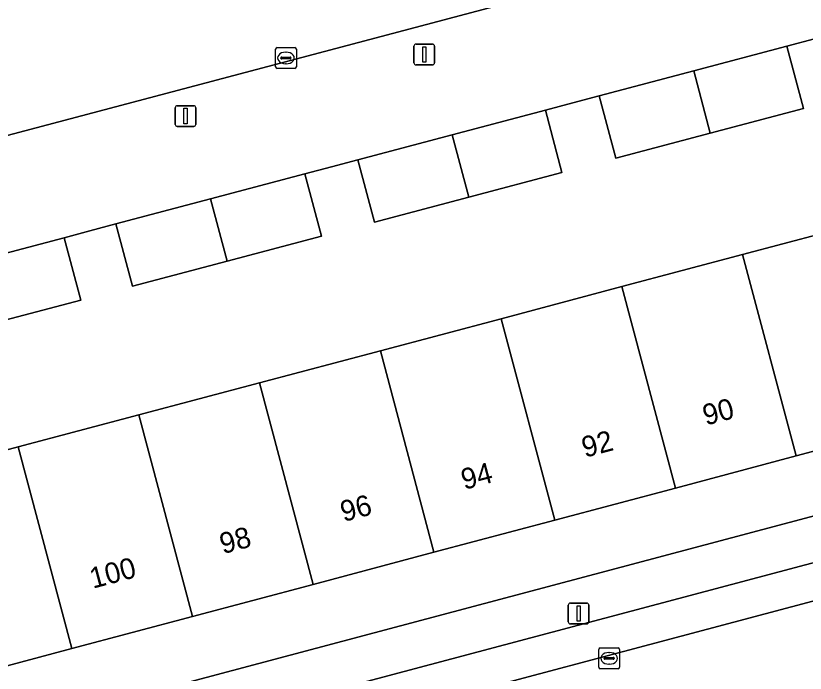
# Model space of a CAD drawing. Extents: x 162542 to 163147, y 380779 to 381521.
# Drawn here: x 162694.02 to 162731.96, y 381121.27 to 381152.86 of the extents above; entities that cross this region are included whole.
import ezdxf

# ---------------------------------------------------------------- set-up
doc = ezdxf.new("R2010")
doc.units = 0
for name, color, linetype in [('IMGEO_Erf', 7, 'Continuous'), ('IMGEO_Kolk', 7, 'Continuous'), ('IMGEO_Lichtmast', 7, 'Continuous'), ('IMGEO_Pand', 7, 'Continuous'), ('IMGEO_Pand_nummerreeks', 7, 'Continuous'), ('IMGEO_Parkeervlak_open', 7, 'Continuous'), ('IMGEO_Rijbaan_lokaal_open', 7, 'Continuous'), ('IMGEO_Voetpad_open', 7, 'Continuous')]:
    doc.layers.add(name, color=color, linetype=linetype)

msp = doc.modelspace()

# ---------------------------------------------------------------- linework, layer by layer
at = {"layer": 'IMGEO_Erf'}
for points in [[(162688.324, 381130.598), (162694.128, 381132.14), (162699.931, 381133.681), (162705.735, 381135.222), (162711.539, 381136.764), (162717.343, 381138.305), (162723.146, 381139.847), (162728.95, 381141.388), (162734.754, 381142.93), (162740.558, 381144.471), (162746.516, 381146.053), (162744.969, 381151.884), (162744.174, 381154.881)], [(162732.404, 381151.76), (162731.076, 381151.408), (162731.872, 381148.412), (162727.397, 381147.225), (162722.851, 381146.02), (162722.057, 381149.017), (162720.795, 381148.682), (162719.469, 381148.33), (162720.266, 381145.334), (162715.788, 381144.147), (162711.258, 381142.946), (162710.46, 381145.942), (162709.186, 381145.604), (162707.914, 381145.267), (162708.711, 381142.271), (162704.179, 381141.069), (162699.629, 381139.863), (162698.832, 381142.859), (162697.578, 381142.526), (162696.34, 381142.198), (162697.138, 381139.202), (162692.57, 381137.991)]]:
    msp.add_lwpolyline(points, dxfattribs=at)
msp.add_lwpolyline([(162749.869, 381133.472), (162749.085, 381136.384), (162743.131, 381134.8), (162737.328, 381133.255), (162731.525, 381131.711), (162725.722, 381130.167), (162719.919, 381128.623), (162714.116, 381127.079), (162708.313, 381125.534), (162702.51, 381123.99), (162696.707, 381122.446), (162690.904, 381120.902), (162684.977, 381119.324), (162684.888, 381119.301), (162684.115, 381122.206), (162678.746, 381120.787), (162680.279, 381114.986), (162685.734, 381116.428)], close=True, dxfattribs=at)
at = {"layer": 'IMGEO_Kolk'}
for p, q in [((162706.577, 381151.337), (162707.429, 381151.337)), ((162706.502, 381150.411), (162706.502, 381151.263)), ((162706.99, 381151.117), (162707.015, 381151.117)), ((162707.503, 381151.263), (162707.503, 381150.411)), ((162706.761, 381150.831), (162706.761, 381150.843)), ((162707.199, 381150.794), (162706.801, 381150.794)), ((162706.804, 381150.88), (162707.202, 381150.88)), ((162707.013, 381150.557), (162706.988, 381150.557)), ((162707.245, 381150.843), (162707.245, 381150.831)), ((162707.429, 381150.337), (162706.577, 381150.337)), ((162722.111, 381122.48), (162722.963, 381122.48)), ((162722.036, 381121.554), (162722.036, 381122.406)), ((162722.524, 381122.26), (162722.549, 381122.26)), ((162723.037, 381122.406), (162723.037, 381121.554)), ((162722.295, 381121.974), (162722.295, 381121.986)), ((162722.733, 381121.937), (162722.335, 381121.937)), ((162722.338, 381122.023), (162722.736, 381122.023)), ((162722.779, 381121.986), (162722.779, 381121.974)), ((162722.963, 381121.48), (162722.111, 381121.48)), ((162722.547, 381121.7), (162722.522, 381121.7))]:
    msp.add_line(p, q, dxfattribs=at)
for points in [[(162706.577, 381151.337), (162707.429, 381151.337)], [(162706.502, 381150.411), (162706.502, 381151.263)], [(162707.503, 381151.263), (162707.503, 381150.411)], [(162707.429, 381150.337), (162706.577, 381150.337)], [(162722.111, 381122.48), (162722.963, 381122.48)], [(162722.036, 381121.554), (162722.036, 381122.406)], [(162723.037, 381122.406), (162723.037, 381121.554)], [(162722.963, 381121.48), (162722.111, 381121.48)]]:
    msp.add_lwpolyline(points, dxfattribs=at)
for centre, radius, start, end in [((162706.579, 381151.261), 0.0765, 91.552, 178.448), ((162706.579, 381151.261), 0.0765, 91.552, 178.448), ((162707.427, 381151.261), 0.0765, 1.552, 88.448), ((162707.427, 381151.261), 0.0765, 1.552, 88.448), ((162706.801, 381150.84), 0.0403, 85.8775, 175.7526), ((162706.798, 381150.83), 0.0366, 178.938, 274.7102), ((162707.202, 381150.837), 0.043, 264.8664, 352.4533), ((162707.206, 381150.842), 0.0386, 1.7309, 96.639), ((162706.579, 381150.413), 0.0765, 181.552, 268.448), ((162706.579, 381150.413), 0.0765, 181.552, 268.448), ((162707.427, 381150.413), 0.0765, 271.552, 358.448), ((162707.427, 381150.413), 0.0765, 271.552, 358.448), ((162722.113, 381122.404), 0.0765, 91.552, 178.448), ((162722.113, 381122.404), 0.0765, 91.552, 178.448), ((162722.961, 381122.404), 0.0765, 1.552, 88.448), ((162722.961, 381122.404), 0.0765, 1.552, 88.448), ((162722.335, 381121.983), 0.0403, 85.8775, 175.7526), ((162722.332, 381121.973), 0.0366, 178.938, 274.7102), ((162722.736, 381121.98), 0.043, 264.8664, 352.4533), ((162722.74, 381121.985), 0.0386, 1.7309, 96.639), ((162722.113, 381121.556), 0.0765, 181.552, 268.448), ((162722.113, 381121.556), 0.0765, 181.552, 268.448), ((162722.961, 381121.556), 0.0765, 271.552, 358.448), ((162722.961, 381121.556), 0.0765, 271.552, 358.448)]:
    msp.add_arc(centre, radius, start, end, dxfattribs=at)
for centre, major_axis, ratio, start_param, end_param in [((162706.989, 381150.837), (-0.387, 0.002), 0.722429, 4.712389, 7.853982), ((162707.014, 381150.837), (-0.39, 0.002), 0.717154, 1.570796, 4.712389), ((162722.523, 381121.98), (-0.387, 0.002), 0.722429, 4.712389, 7.853982), ((162722.548, 381121.98), (-0.39, 0.002), 0.717154, 1.570796, 4.712389)]:
    msp.add_ellipse(centre, major_axis=major_axis, ratio=ratio, start_param=start_param, end_param=end_param, dxfattribs=at)
at = {"layer": 'IMGEO_Lichtmast'}
for p, q in [((162713.156, 381150.604), (162713.156, 381151.404)), ((162713.156, 381151.404), (162713.156, 381150.604)), ((162713.256, 381151.504), (162714.046, 381151.504)), ((162714.046, 381151.504), (162713.256, 381151.504)), ((162714.146, 381151.404), (162714.146, 381150.604)), ((162714.146, 381150.604), (162714.146, 381151.404)), ((162714.046, 381150.504), (162713.256, 381150.504)), ((162713.256, 381150.504), (162714.046, 381150.504)), ((162701.68, 381147.644), (162701.68, 381148.444)), ((162701.68, 381148.444), (162701.68, 381147.644)), ((162701.78, 381148.544), (162702.57, 381148.544)), ((162702.57, 381148.544), (162701.78, 381148.544)), ((162702.67, 381148.444), (162702.67, 381147.644)), ((162702.67, 381147.644), (162702.67, 381148.444)), ((162702.57, 381147.544), (162701.78, 381147.544)), ((162701.78, 381147.544), (162702.57, 381147.544)), ((162720.573, 381123.736), (162720.573, 381124.536)), ((162720.573, 381124.536), (162720.573, 381123.736)), ((162720.673, 381124.636), (162721.463, 381124.636)), ((162721.463, 381124.636), (162720.673, 381124.636)), ((162721.563, 381124.536), (162721.563, 381123.736)), ((162721.563, 381123.736), (162721.563, 381124.536)), ((162721.463, 381123.636), (162720.673, 381123.636)), ((162720.673, 381123.636), (162721.463, 381123.636))]:
    msp.add_line(p, q, dxfattribs=at)
for points in [[(162713.576, 381151.379), (162713.726, 381151.379), (162713.726, 381150.629), (162713.576, 381150.629), (162713.576, 381151.379)], [(162702.1, 381148.419), (162702.25, 381148.419), (162702.25, 381147.669), (162702.1, 381147.669), (162702.1, 381148.419)], [(162720.993, 381124.511), (162721.143, 381124.511), (162721.143, 381123.761), (162720.993, 381123.761), (162720.993, 381124.511)]]:
    msp.add_lwpolyline(points, dxfattribs=at)
for centre, start, end in [((162713.256, 381151.404), 90, 180), ((162713.256, 381151.404), 90, 180), ((162714.046, 381151.404), 0, 90), ((162714.046, 381151.404), 360, 90), ((162713.256, 381150.604), 180, 270), ((162713.256, 381150.604), 180, 270), ((162714.046, 381150.604), 270, 0), ((162714.046, 381150.604), 270, 0), ((162701.78, 381148.444), 90, 180), ((162701.78, 381148.444), 90, 180), ((162702.57, 381148.444), 0, 90), ((162702.57, 381148.444), 360, 90), ((162701.78, 381147.644), 180, 270), ((162701.78, 381147.644), 180, 270), ((162702.57, 381147.644), 270, 0), ((162702.57, 381147.644), 270, 0), ((162720.673, 381124.536), 90, 180), ((162720.673, 381124.536), 90, 180), ((162721.463, 381124.536), 0, 90), ((162721.463, 381124.536), 360, 90), ((162720.673, 381123.736), 180, 270), ((162720.673, 381123.736), 180, 270), ((162721.463, 381123.736), 270, 0), ((162721.463, 381123.736), 270, 0)]:
    msp.add_arc(centre, 0.1, start, end, dxfattribs=at)
at = {"layer": 'IMGEO_Pand'}
for points in [[(162731.076, 381151.408), (162726.6, 381150.221), (162727.397, 381147.225), (162731.872, 381148.412)], [(162726.6, 381150.221), (162722.057, 381149.017), (162722.851, 381146.02), (162727.397, 381147.225)], [(162719.469, 381148.33), (162714.991, 381147.143), (162715.788, 381144.147), (162720.266, 381145.334)], [(162714.991, 381147.143), (162710.46, 381145.942), (162711.258, 381142.946), (162715.788, 381144.147)], [(162707.914, 381145.267), (162703.382, 381144.065), (162704.179, 381141.069), (162708.711, 381142.271)], [(162703.382, 381144.065), (162698.832, 381142.859), (162699.629, 381139.863), (162704.179, 381141.069)], [(162734.754, 381142.93), (162728.95, 381141.388), (162731.525, 381131.711), (162737.328, 381133.255)], [(162696.34, 381142.198), (162691.773, 381140.987), (162692.57, 381137.991), (162697.138, 381139.202)], [(162723.146, 381139.847), (162725.722, 381130.167), (162731.525, 381131.711), (162728.95, 381141.388)], [(162723.146, 381139.847), (162717.343, 381138.305), (162719.919, 381128.623), (162725.722, 381130.167)], [(162719.919, 381128.623), (162717.343, 381138.305), (162711.539, 381136.764), (162714.116, 381127.079)], [(162711.539, 381136.764), (162705.735, 381135.222), (162708.313, 381125.534), (162714.116, 381127.079)], [(162699.931, 381133.681), (162702.51, 381123.99), (162708.313, 381125.534), (162705.735, 381135.222)], [(162699.931, 381133.681), (162694.128, 381132.14), (162696.707, 381122.446), (162702.51, 381123.99)], [(162690.904, 381120.902), (162696.707, 381122.446), (162694.128, 381132.14), (162688.324, 381130.598)]]:
    msp.add_lwpolyline(points, close=True, dxfattribs=at)
at = {"layer": 'IMGEO_Parkeervlak_open'}
for points in [[(162750.234, 381131.33), (162666.499, 381109.073), (162666.934, 381107.34), (162774.201, 381135.871), (162796.063, 381141.696), (162882.877, 381164.808), (162901.876, 381169.92), (162904.167, 381170.544), (162903.648, 381172.331), (162882.303, 381166.521), (162850.91, 381158.201), (162843.113, 381156.134), (162825.633, 381151.487), (162819.826, 381149.913), (162790.747, 381142.166), (162781.519, 381139.707), (162755.957, 381132.897)], [(162720.795, 381148.682), (162722.057, 381149.017), (162726.6, 381150.221), (162731.076, 381151.408), (162732.404, 381151.76), (162733.695, 381152.102), (162738.209, 381153.299), (162742.727, 381154.497), (162744.174, 381154.881), (162742.8, 381160.155), (162686.579, 381145.246), (162685.757, 381144.981), (162687.17, 381139.767), (162687.51, 381139.857), (162691.773, 381140.987), (162696.34, 381142.198), (162697.578, 381142.526), (162698.832, 381142.859), (162703.382, 381144.065), (162707.914, 381145.267), (162709.186, 381145.604), (162710.46, 381145.942), (162714.991, 381147.143), (162719.469, 381148.33)]]:
    msp.add_lwpolyline(points, close=True, dxfattribs=at)
at = {"layer": 'IMGEO_Rijbaan_lokaal_open'}
for points in [[(162676.015, 381154.427), (162676.822, 381151.351), (162677.911, 381147.157), (162678.692, 381144.15), (162679.725, 381140.171), (162680.329, 381137.953), (162684.722, 381139.117), (162685.969, 381139.448), (162687.17, 381139.767), (162685.757, 381144.981), (162686.579, 381145.246), (162742.8, 381160.155)], [(162752.751, 381124.999), (162754.693, 381125.516), (162758.591, 381126.553), (162768.331, 381129.144), (162769.49, 381129.452), (162775.451, 381131.037), (162774.201, 381135.871), (162666.934, 381107.34), (162664.853, 381106.777)]]:
    msp.add_lwpolyline(points, dxfattribs=at)
at = {"layer": 'IMGEO_Voetpad_open'}
for points in [[(162749.869, 381133.472), (162685.734, 381116.428)], [(162666.934, 381107.34), (162666.499, 381109.073), (162750.234, 381131.33)]]:
    msp.add_lwpolyline(points, dxfattribs=at)

# ---------------------------------------------------------------- texts
at = {"layer": 'IMGEO_Pand_nummerreeks'}
for s, p in [('90', (162727.183, 381133.163)), ('92', (162721.371, 381131.617)), ('94', (162715.574, 381130.074)), ('96', (162709.771, 381128.53)), ('98', (162703.971, 381126.986)), ('100', (162697.723, 381125.324))]:
    msp.add_text(s, height=1, rotation=14.9015, dxfattribs=at).set_placement(p)

doc.saveas('drawing.dxf')
